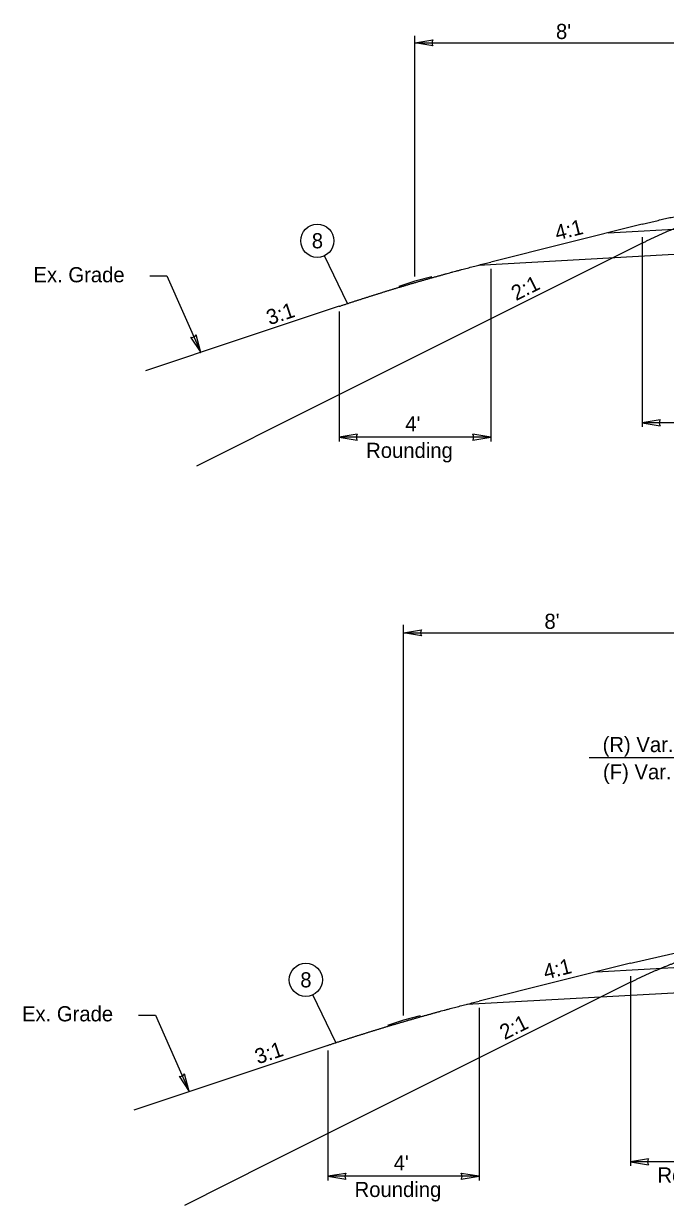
# Model space of a CAD drawing. Extents: x -219 to 803, y -225 to 180.
# Drawn here: x -175.23 to -158.28, y -39.7 to -8.5 of the extents above; entities that cross this region are included whole.
import ezdxf

# ---------------------------------------------------------------- set-up
doc = ezdxf.new("R2010")
doc.units = 0
doc.layers.add('Level 16', color=7, linetype='Continuous')
doc.layers.add('XS_X_Pavt', color=7, linetype='Continuous')

msp = doc.modelspace()

# ---------------------------------------------------------------- linework, layer by layer
at = {"layer": 'Level 16'}
for p, q in [((-164.894, -15.182), (-164.894, -8.83)), ((-164.894, -9.014), (-164.42, -8.935)), ((-164.419, -9.093), (-164.894, -9.014)), ((-164.894, -9.014), (-156.894, -9.014)), ((-164.42, -8.935), (-164.42, -8.935)), ((-158.894, -13.8), (-162.894, -14.8)), ((-159.79, -14.024), (-154.894, -13.75)), ((-158.894, -14.3), (-167.611, -18.659)), ((-158.894, -14.141), (-158.894, -19.152)), ((-166.68, -15.896), (-167.286, -14.632)), ((-163.216, -14.884), (-154.394, -14.39)), ((-171.895, -15.166), (-171.445, -15.166)), ((-171.445, -15.166), (-170.555, -17.187)), ((-164.452, -15.19), (-164.894, -15.3)), ((-162.894, -14.978), (-162.894, -19.534)), ((-164.894, -15.3), (-165.317, -15.441)), ((-166.894, -15.967), (-169.456, -16.821)), ((-166.894, -16.106), (-166.894, -19.534)), ((-169.456, -16.821), (-172.017, -17.675)), ((-170.82, -16.785), (-170.555, -17.187)), ((-170.555, -17.187), (-170.675, -16.722)), ((-170.675, -16.722), (-170.675, -16.722)), ((-167.611, -18.659), (-170.664, -20.185)), ((-158.419, -18.964), (-158.894, -19.043)), ((-158.894, -19.043), (-158.42, -19.122)), ((-154.894, -19.043), (-158.894, -19.043)), ((-158.42, -19.122), (-158.42, -19.122)), ((-166.419, -19.346), (-166.894, -19.425)), ((-166.894, -19.425), (-166.42, -19.504)), ((-162.894, -19.425), (-166.894, -19.425)), ((-166.42, -19.504), (-166.42, -19.504)), ((-163.369, -19.504), (-162.894, -19.425)), ((-162.894, -19.425), (-163.367, -19.346)), ((-163.367, -19.346), (-163.367, -19.346)), ((-165.198, -34.694), (-165.198, -24.373)), ((-165.198, -24.587), (-164.725, -24.508)), ((-164.723, -24.666), (-165.198, -24.587)), ((-165.198, -24.587), (-157.198, -24.587)), ((-164.725, -24.508), (-164.725, -24.508)), ((-154.198, -27.887), (-160.292, -27.887)), ((-159.198, -33.312), (-163.198, -34.312)), ((-160.095, -33.536), (-155.198, -33.262)), ((-159.198, -33.653), (-159.198, -38.664)), ((-159.198, -33.812), (-168.724, -38.575)), ((-163.52, -34.396), (-154.698, -33.902)), ((-166.984, -35.408), (-167.59, -34.144)), ((-163.198, -34.49), (-163.198, -39.046)), ((-172.2, -34.678), (-171.75, -34.678)), ((-171.75, -34.678), (-170.86, -36.699)), ((-165.198, -34.812), (-165.621, -34.953)), ((-164.757, -34.702), (-165.198, -34.812)), ((-167.198, -35.479), (-169.76, -36.333)), ((-167.198, -35.618), (-167.198, -39.046)), ((-169.76, -36.333), (-172.322, -37.187)), ((-171.125, -36.297), (-170.86, -36.699)), ((-170.86, -36.699), (-170.98, -36.235)), ((-170.98, -36.235), (-170.98, -36.235)), ((-168.724, -38.575), (-170.981, -39.704)), ((-158.723, -38.476), (-159.198, -38.555)), ((-159.198, -38.555), (-158.725, -38.634)), ((-155.198, -38.555), (-159.198, -38.555)), ((-158.725, -38.634), (-158.725, -38.634)), ((-166.723, -38.858), (-167.198, -38.937)), ((-167.198, -38.937), (-166.725, -39.016)), ((-163.198, -38.937), (-167.198, -38.937)), ((-163.673, -39.016), (-163.198, -38.937)), ((-163.198, -38.937), (-163.672, -38.858)), ((-163.672, -38.858), (-163.672, -38.858)), ((-166.725, -39.016), (-166.725, -39.016))]:
    msp.add_line(p, q, dxfattribs=at)
for centre in [(-167.475, -14.237), (-167.779, -33.749)]:
    msp.add_circle(centre, 0.438, dxfattribs=at)
for centre, start, end in [((-164.299, -9.013), 147.1412, 213.822), ((-170.795, -16.644), 260.1439, 326.8246), ((-158.299, -19.044), 146.178, 212.8588), ((-166.299, -19.426), 146.178, 212.8588), ((-163.488, -19.424), 326.178, 32.8588), ((-164.604, -24.586), 147.1412, 213.822), ((-171.1, -36.156), 260.1439, 326.8246), ((-158.604, -38.556), 146.178, 212.8588), ((-166.604, -38.938), 146.178, 212.8588), ((-163.793, -38.936), 326.178, 32.8588)]:
    msp.add_arc(centre, 0.144, start, end, dxfattribs=at)
for points in [[(-158.894, -13.8), (-158.817, -13.781), (-158.74, -13.762), (-158.663, -13.743), (-158.586, -13.725), (-158.509, -13.707), (-158.432, -13.689), (-158.355, -13.671), (-158.278, -13.653), (-158.201, -13.636), (-158.124, -13.619), (-158.047, -13.602), (-157.971, -13.585), (-157.894, -13.569), (-157.817, -13.552), (-157.74, -13.536), (-157.663, -13.521), (-157.586, -13.505), (-157.509, -13.49), (-157.432, -13.475), (-157.355, -13.46), (-157.278, -13.445), (-157.201, -13.431), (-157.124, -13.416), (-157.047, -13.402), (-156.971, -13.389), (-156.894, -13.375), (-156.817, -13.362), (-156.74, -13.348), (-156.663, -13.336), (-156.586, -13.323), (-156.509, -13.31), (-156.432, -13.298), (-156.355, -13.286), (-156.278, -13.274), (-156.201, -13.263), (-156.124, -13.251), (-156.047, -13.24), (-155.971, -13.229), (-155.894, -13.219), (-155.817, -13.208), (-155.74, -13.198), (-155.663, -13.188), (-155.586, -13.178), (-155.509, -13.169), (-155.432, -13.159), (-155.355, -13.15), (-155.278, -13.141), (-155.201, -13.133), (-155.124, -13.124), (-155.047, -13.116), (-154.971, -13.108), (-154.894, -13.1)], [(-158.894, -14.3), (-158.817, -14.262), (-158.74, -14.224), (-158.663, -14.187), (-158.586, -14.151), (-158.509, -14.115), (-158.432, -14.08), (-158.355, -14.045), (-158.278, -14.011), (-158.201, -13.978), (-158.124, -13.945), (-158.047, -13.913), (-157.971, -13.881), (-157.894, -13.85), (-157.817, -13.819), (-157.74, -13.79), (-157.663, -13.76), (-157.586, -13.732), (-157.509, -13.704), (-157.432, -13.676), (-157.355, -13.649), (-157.278, -13.623), (-157.201, -13.597), (-157.124, -13.572), (-157.047, -13.547), (-156.971, -13.523), (-156.894, -13.5), (-156.817, -13.477), (-156.74, -13.455), (-156.663, -13.433), (-156.586, -13.412), (-156.509, -13.392), (-156.432, -13.372), (-156.355, -13.353), (-156.278, -13.334), (-156.201, -13.316), (-156.124, -13.299), (-156.047, -13.282), (-155.971, -13.266), (-155.894, -13.25), (-155.817, -13.235), (-155.74, -13.22), (-155.663, -13.206), (-155.586, -13.193), (-155.509, -13.18), (-155.432, -13.168), (-155.355, -13.157), (-155.278, -13.146), (-155.201, -13.135), (-155.124, -13.126), (-155.047, -13.117), (-154.971, -13.108), (-154.894, -13.1)], [(-166.894, -15.967), (-166.817, -15.941), (-166.74, -15.916), (-166.663, -15.89), (-166.586, -15.865), (-166.509, -15.84), (-166.432, -15.815), (-166.355, -15.79), (-166.278, -15.765), (-166.201, -15.741), (-166.124, -15.716), (-166.047, -15.692), (-165.971, -15.668), (-165.894, -15.644), (-165.817, -15.62), (-165.74, -15.596), (-165.663, -15.572), (-165.586, -15.549), (-165.509, -15.525), (-165.432, -15.502), (-165.355, -15.478), (-165.278, -15.455), (-165.201, -15.432), (-165.124, -15.41), (-165.047, -15.387), (-164.971, -15.364), (-164.894, -15.342), (-164.817, -15.319), (-164.74, -15.297), (-164.663, -15.275), (-164.586, -15.253), (-164.509, -15.231), (-164.432, -15.209), (-164.355, -15.188), (-164.278, -15.166), (-164.201, -15.145), (-164.124, -15.123), (-164.047, -15.102), (-163.971, -15.081), (-163.894, -15.06), (-163.817, -15.04), (-163.74, -15.019), (-163.663, -14.998), (-163.586, -14.978), (-163.509, -14.958), (-163.432, -14.938), (-163.355, -14.918), (-163.278, -14.898), (-163.201, -14.878), (-163.124, -14.858), (-163.047, -14.839), (-162.971, -14.819), (-162.894, -14.8)], [(-159.198, -33.312), (-159.121, -33.293), (-159.044, -33.274), (-158.967, -33.255), (-158.89, -33.237), (-158.814, -33.219), (-158.737, -33.201), (-158.66, -33.183), (-158.583, -33.165), (-158.506, -33.148), (-158.429, -33.131), (-158.352, -33.114), (-158.275, -33.097), (-158.198, -33.081), (-158.121, -33.065), (-158.044, -33.049), (-157.967, -33.033), (-157.89, -33.017), (-157.814, -33.002), (-157.737, -32.987), (-157.66, -32.972), (-157.583, -32.957), (-157.506, -32.943), (-157.429, -32.928), (-157.352, -32.914), (-157.275, -32.901), (-157.198, -32.887), (-157.121, -32.874), (-157.044, -32.861), (-156.967, -32.848), (-156.89, -32.835), (-156.814, -32.822), (-156.737, -32.81), (-156.66, -32.798), (-156.583, -32.786), (-156.506, -32.775), (-156.429, -32.763), (-156.352, -32.752), (-156.275, -32.741), (-156.198, -32.731), (-156.121, -32.72), (-156.044, -32.71), (-155.967, -32.7), (-155.89, -32.69), (-155.814, -32.681), (-155.737, -32.671), (-155.66, -32.662), (-155.583, -32.653), (-155.506, -32.645), (-155.429, -32.636), (-155.352, -32.628), (-155.275, -32.62), (-155.198, -32.612)], [(-159.198, -33.812), (-159.121, -33.774), (-159.044, -33.736), (-158.967, -33.699), (-158.89, -33.663), (-158.814, -33.627), (-158.737, -33.592), (-158.66, -33.557), (-158.583, -33.523), (-158.506, -33.49), (-158.429, -33.457), (-158.352, -33.425), (-158.275, -33.393), (-158.198, -33.362), (-158.121, -33.332), (-158.044, -33.302), (-157.967, -33.272), (-157.89, -33.244), (-157.814, -33.216), (-157.737, -33.188), (-157.66, -33.161), (-157.583, -33.135), (-157.506, -33.109), (-157.429, -33.084), (-157.352, -33.059), (-157.275, -33.035), (-157.198, -33.012), (-157.121, -32.989), (-157.044, -32.967), (-156.967, -32.945), (-156.89, -32.924), (-156.814, -32.904), (-156.737, -32.884), (-156.66, -32.865), (-156.583, -32.846), (-156.506, -32.828), (-156.429, -32.811), (-156.352, -32.794), (-156.275, -32.778), (-156.198, -32.762), (-156.121, -32.747), (-156.044, -32.732), (-155.967, -32.719), (-155.89, -32.705), (-155.814, -32.692), (-155.737, -32.68), (-155.66, -32.669), (-155.583, -32.658), (-155.506, -32.648), (-155.429, -32.638), (-155.352, -32.629), (-155.275, -32.62), (-155.198, -32.612)], [(-167.198, -35.479), (-167.121, -35.453), (-167.044, -35.428), (-166.967, -35.402), (-166.89, -35.377), (-166.814, -35.352), (-166.737, -35.327), (-166.66, -35.302), (-166.583, -35.278), (-166.506, -35.253), (-166.429, -35.228), (-166.352, -35.204), (-166.275, -35.18), (-166.198, -35.156), (-166.121, -35.132), (-166.044, -35.108), (-165.967, -35.084), (-165.89, -35.061), (-165.814, -35.037), (-165.737, -35.014), (-165.66, -34.991), (-165.583, -34.967), (-165.506, -34.944), (-165.429, -34.922), (-165.352, -34.899), (-165.275, -34.876), (-165.198, -34.854), (-165.121, -34.831), (-165.044, -34.809), (-164.967, -34.787), (-164.89, -34.765), (-164.814, -34.743), (-164.737, -34.721), (-164.66, -34.7), (-164.583, -34.678), (-164.506, -34.657), (-164.429, -34.635), (-164.352, -34.614), (-164.275, -34.593), (-164.198, -34.572), (-164.121, -34.552), (-164.044, -34.531), (-163.967, -34.51), (-163.89, -34.49), (-163.814, -34.47), (-163.737, -34.45), (-163.66, -34.43), (-163.583, -34.41), (-163.506, -34.39), (-163.429, -34.37), (-163.352, -34.351), (-163.275, -34.331), (-163.198, -34.312)]]:
    msp.add_spline(points, degree=3, dxfattribs=at)
at = {"layer": 'XS_X_Pavt'}
for points in [[(-164.891, -9.015), (-164.892, -9.013)], [(-164.89, -9.014), (-164.892, -9.013)], [(-170.557, -17.184), (-170.555, -17.185)], [(-170.557, -17.185), (-170.555, -17.186)], [(-158.891, -19.042), (-158.892, -19.043)], [(-158.89, -19.042), (-158.892, -19.043)], [(-166.891, -19.424), (-166.892, -19.425)], [(-166.89, -19.424), (-166.892, -19.425)], [(-162.897, -19.426), (-162.895, -19.425)], [(-162.896, -19.426), (-162.895, -19.425)], [(-165.196, -24.588), (-165.197, -24.587)], [(-165.195, -24.588), (-165.197, -24.587)], [(-170.862, -36.696), (-170.86, -36.698)], [(-170.861, -36.697), (-170.86, -36.698)], [(-159.196, -38.554), (-159.197, -38.555)], [(-159.195, -38.554), (-159.197, -38.555)], [(-167.196, -38.936), (-167.197, -38.937)], [(-167.195, -38.936), (-167.197, -38.937)], [(-163.202, -38.938), (-163.2, -38.937)], [(-163.201, -38.938), (-163.2, -38.937)]]:
    msp.add_lwpolyline(points, dxfattribs=at)

# ---------------------------------------------------------------- texts
at = {"layer": 'Level 16'}
for s, p in [("8'", (-161.169, -8.911)), ('8', (-167.62, -14.437)), ('Ex. Grade', (-174.972, -15.334)), ("4'", (-165.151, -19.271)), ('Rounding', (-166.184, -19.971)), ("8'", (-161.474, -24.484)), ("(R) Var. 2.2' to 6.8'", (-159.937, -27.737)), ("(F) Var. 6.4' to 2.2'", (-159.928, -28.457)), ('8', (-167.924, -33.949)), ('Ex. Grade', (-175.276, -34.846)), ("4'", (-165.456, -38.783)), ('Rounding', (-158.489, -39.101)), ('Rounding', (-166.489, -39.483))]:
    msp.add_text(s, height=0.4, dxfattribs=at).set_placement(p)
for s, rotation, p in [('4:1', 14.0362, (-161.142, -14.231)), ('2:1', 26.5651, (-162.223, -15.83)), ('3:1', 18.4349, (-168.739, -16.47)), ('4:1', 14.0362, (-161.446, -33.743)), ('2:1', 26.5651, (-162.528, -35.342)), ('3:1', 18.4349, (-169.044, -35.983))]:
    msp.add_text(s, height=0.4, rotation=rotation, dxfattribs=at).set_placement(p)

doc.saveas('drawing.dxf')
